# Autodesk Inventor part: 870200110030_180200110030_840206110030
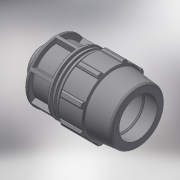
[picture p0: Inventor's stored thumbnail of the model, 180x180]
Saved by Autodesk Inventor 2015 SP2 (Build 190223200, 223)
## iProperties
Created: 2017-02
Part Number: 870200110030_180200110030_840206110030
Material: Generic
Description: PLASSON MALE ADAPTOR 110-3"
Document SubType Name: Modeling
Designer: KIM
Mass: 964.158 g
Surface Area: 1468.9 cm^2
Volume: 964.158 cm^3
Density: 1 g/cm^3
Appearance: Default
Author: KIM
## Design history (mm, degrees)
derived "87020.ipt"
feature "Solid1::87020.ipt"
tag "TaggingFeature1"
body "Solid1"
other parameters: "d4" = 37, "d5" = 64.75, "d7" = 181, "d8" = 135.75, "d9" = 37, "d11" = 7.4, "d12" = 144.8, "d13" = 120 deg, "d14" = 143, "d15" = 6 deg, "d16" = 162.9, "d18" = 5.5, "d19" = 35 deg, "d20" = 17.5 deg, "d21" = 168.33, "d23" = 0, "d25" = 360 deg, "d27" = 3.62, "d34" = 9.05, "d36" = 0, "d42" = 64.75, "d43" = 5.43, "d46" = 3.3, "d49" = 215, "d51" = 259, "d52" = 33, "d53" = 2.2, "d55" = 360 deg, "d57" = 87.884, "d58" = 61.5188, "d59" = 51.8, "d61" = 159.642, "d62" = 5.98, "d63" = 5.98, "d66" = 11.96, "E_" = 181, "H_" = 259, "l_" = 215, "l_2" = 33, "R_" = 87.884, "d60" = 29.9
